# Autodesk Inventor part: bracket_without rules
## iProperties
Created: 2007-08
Part Number: bracket_without rules
Document SubType Name: Modeling
Designer: DaveR
Density: 1 g/cm^3
Mass: 7.59456 g
Surface Area: 56.7093 cm^2
Volume: 7.59456 cm^3
Author: DaveR
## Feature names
1. main_body [Extrusion]
2. Chamfers
3. base_hole [Hole]
4. base_hole_pattern [Rectangular Pattern]
5. flange_hole [Hole]
6. flange_hole_pattern [Rectangular Pattern]
7. Inside_fillet [Fillet]
8. Outside_fillet [Fillet]
9. rib_pattern [Rectangular Pattern]
